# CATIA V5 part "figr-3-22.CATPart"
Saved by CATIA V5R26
Part number: Part1
Bounding box of the stored display mesh (mm): x -100.656 to 120.085, y -71.941 to 77.746, z 0 to 0
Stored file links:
  D:\_Deepak\CATIA\CATIA V5-6R2016_Deepak\Resources\Part files\Partfiles\c03_catia_v5_6r2016_prt\figr-3-22.CATPart
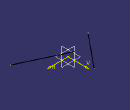
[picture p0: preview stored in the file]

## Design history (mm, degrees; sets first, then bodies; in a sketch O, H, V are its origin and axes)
Body1 (main body)
  Sketch1 on xy-plane, origin (0, 0, 0), H (1, 0, 0), V (0, 1, 0)
    line L1 (-9.7143, 77.7457) -> (-100.6564, -33.7935)
    line L2 (-27.4893, -3.1098) -> (120.0849, -71.9407)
